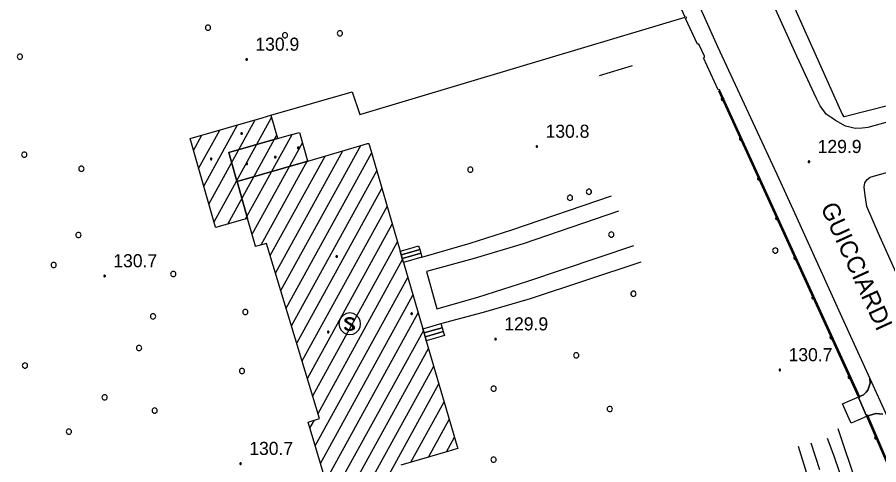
# Model space of a CAD drawing. Extents: x 513373 to 514978, y 5038576 to 5040180.
# Drawn here: x 513452.1 to 513550.7, y 5038668.6 to 5038719.9 of the extents above; entities that cross this region are included whole.
import ezdxf

# ---------------------------------------------------------------- set-up
doc = ezdxf.new("R2010")
doc.units = 0
for name, color, linetype in [('2010300', 7, 'Continuous'), ('3010204', 7, 'Continuous'), ('3030201', 7, 'Continuous'), ('B1211', 7, 'Continuous'), ('B12210', 7, 'Continuous'), ('C1131', 7, 'Continuous'), ('C12211', 7, 'Continuous'), ('C211113', 7, 'Continuous'), ('C211123', 7, 'Continuous'), ('C2911', 7, 'Continuous'), ('CAMP_C12211', 7, 'Continuous'), ('Default', 7, 'Continuous'), ('F12107', 7, 'Continuous'), ('F12131', 7, 'Continuous'), ('F12132', 7, 'Continuous'), ('G4315', 7, 'Continuous'), ('TOP500', 7, 'Continuous'), ('TOP920', 7, 'Continuous')]:
    doc.layers.add(name, color=color, linetype=linetype)

# ---------------------------------------------------------------- blocks, each defined once
blk = doc.blocks.new('CAMP_2F84D089')
at = {"layer": 'CAMP_C12211'}
for p, q in [((-7.696, 40.351), (-1.13, 52.294)), ((-8.876, 44.431), (-5.017, 51.451)), ((-8.286, 42.391), (-2.981, 52.04)), ((-9.467, 46.471), (-7.052, 50.862)), ((-4.088, 40.686), (1.234, 50.367)), ((-10.057, 48.511), (-9.088, 50.273)), ((-6.124, 40.097), (-0.544, 50.246)), ((-3.345, 38.924), (2.412, 49.395)), ((-0.656, 34.474), (7.048, 48.488)), ((-0.049, 32.464), (9.092, 49.092)), ((-2.306, 37.701), (3.005, 47.36)), ((-1.264, 36.483), (5.005, 47.885)), ((0.558, 30.455), (10.327, 48.226)), ((1.165, 28.446), (10.921, 46.191)), ((1.772, 26.437), (11.514, 44.157)), ((2.379, 24.428), (12.107, 42.122)), ((2.987, 22.418), (12.7, 40.088)), ((3.594, 20.409), (13.294, 38.053)), ((4.201, 18.4), (13.887, 36.019)), ((3.872, 14.688), (14.48, 33.984)), ((4.477, 12.675), (15.073, 31.95)), ((5.082, 10.661), (15.666, 29.915)), ((5.687, 8.648), (16.26, 27.88)), ((1.258, -2.521), (16.853, 25.846)), ((1.852, -4.554), (17.446, 23.811)), ((2.446, -6.588), (18.039, 21.777)), ((14.819, 12.805), (18.633, 19.742)), ((3.267, 16.702), (3.78, 17.634)), ((16.856, 13.396), (19.226, 17.708)), ((18.893, 13.988), (19.819, 15.673))]:
    blk.add_line(p, q, dxfattribs=at)
blk = doc.blocks.new('03080200')
at = {"layer": 'Default'}
for p, q in [((-0.139, 0.046), (-0.146, 0)), ((-0.146, 0), (-0.139, -0.046)), ((-0.118, 0.086), (-0.139, 0.046)), ((-0.086, 0.118), (-0.118, 0.086)), ((-0.046, 0.139), (-0.086, 0.118)), ((0, 0.146), (-0.046, 0.139)), ((-0.042, 0.014), (-0.045, 0)), ((-0.045, 0), (-0.042, -0.014)), ((-0.036, 0.026), (-0.042, 0.014)), ((-0.026, 0.036), (-0.036, 0.026)), ((-0.014, 0.042), (-0.026, 0.036)), ((0, 0.045), (-0.014, 0.042)), ((0.046, 0.139), (0, 0.146)), ((0.014, 0.042), (0, 0.045)), ((0.026, 0.036), (0.014, 0.042)), ((0.036, 0.026), (0.026, 0.036)), ((0.042, 0.014), (0.036, 0.026)), ((0.045, 0), (0.042, 0.014)), ((0.042, -0.014), (0.045, 0)), ((0.086, 0.118), (0.046, 0.139)), ((0.118, 0.086), (0.086, 0.118)), ((0.139, 0.046), (0.118, 0.086)), ((0.146, 0), (0.139, 0.046)), ((0.139, -0.046), (0.146, 0)), ((-0.139, -0.046), (-0.118, -0.086)), ((-0.118, -0.086), (-0.086, -0.118)), ((-0.086, -0.118), (-0.046, -0.139)), ((-0.046, -0.139), (0, -0.146)), ((-0.042, -0.014), (-0.036, -0.026)), ((-0.036, -0.026), (-0.026, -0.036)), ((-0.026, -0.036), (-0.014, -0.042)), ((-0.014, -0.042), (0, -0.045)), ((0, -0.045), (0.014, -0.042)), ((0, -0.146), (0.046, -0.139)), ((0.014, -0.042), (0.026, -0.036)), ((0.026, -0.036), (0.036, -0.026)), ((0.036, -0.026), (0.042, -0.014)), ((0.046, -0.139), (0.086, -0.118)), ((0.086, -0.118), (0.118, -0.086)), ((0.118, -0.086), (0.139, -0.046))]:
    blk.add_line(p, q, dxfattribs=at)
blk = doc.blocks.new('08020400')
at = {"layer": 'Default'}
for p, q in [((-0.086, 0.028), (-0.09, 0)), ((-0.09, 0), (-0.086, -0.028)), ((-0.073, 0.053), (-0.086, 0.028)), ((-0.053, 0.073), (-0.073, 0.053)), ((-0.028, 0.086), (-0.053, 0.073)), ((0, 0.09), (-0.028, 0.086)), ((0.028, 0.086), (0, 0.09)), ((0.053, 0.073), (0.028, 0.086)), ((0.073, 0.053), (0.053, 0.073)), ((0.086, 0.028), (0.073, 0.053)), ((0.09, 0), (0.086, 0.028)), ((0.086, -0.028), (0.09, 0)), ((-0.086, -0.028), (-0.073, -0.053)), ((-0.073, -0.053), (-0.053, -0.073)), ((-0.053, -0.073), (-0.028, -0.086)), ((-0.028, -0.086), (0, -0.09)), ((0, -0.09), (0.028, -0.086)), ((0.028, -0.086), (0.053, -0.073)), ((0.053, -0.073), (0.073, -0.053)), ((0.073, -0.053), (0.086, -0.028))]:
    blk.add_line(p, q, dxfattribs=at)
blk = doc.blocks.new('NSIMB25')
at = {"layer": 'Default'}
for p, q in [((-0.086, 0.028), (-0.09, 0)), ((-0.09, 0), (-0.086, -0.028)), ((-0.073, 0.053), (-0.086, 0.028)), ((-0.053, 0.073), (-0.073, 0.053)), ((-0.028, 0.086), (-0.053, 0.073)), ((0, 0.09), (-0.028, 0.086)), ((0.028, 0.086), (0, 0.09)), ((0.053, 0.073), (0.028, 0.086)), ((0.073, 0.053), (0.053, 0.073)), ((0.086, 0.028), (0.073, 0.053)), ((0.09, 0), (0.086, 0.028)), ((0.086, -0.028), (0.09, 0)), ((-0.086, -0.028), (-0.073, -0.053)), ((-0.073, -0.053), (-0.053, -0.073)), ((-0.053, -0.073), (-0.028, -0.086)), ((-0.028, -0.086), (0, -0.09)), ((0, -0.09), (0.028, -0.086)), ((0.028, -0.086), (0.053, -0.073)), ((0.053, -0.073), (0.073, -0.053)), ((0.073, -0.053), (0.086, -0.028))]:
    blk.add_line(p, q, dxfattribs=at)
blk = doc.blocks.new('05010100')
at = {"layer": 'Default'}
for p, q in [((-0.143, 0.046), (-0.15, 0)), ((-0.15, 0), (-0.143, -0.046)), ((-0.121, 0.088), (-0.143, 0.046)), ((-0.088, 0.121), (-0.121, 0.088)), ((-0.046, 0.143), (-0.088, 0.121)), ((0, 0.15), (-0.046, 0.143)), ((0.046, 0.143), (0, 0.15)), ((0.088, 0.121), (0.046, 0.143)), ((0.121, 0.088), (0.088, 0.121)), ((0.143, 0.046), (0.121, 0.088)), ((0.15, 0), (0.143, 0.046)), ((0.143, -0.046), (0.15, 0)), ((-0.143, -0.046), (-0.121, -0.088)), ((-0.121, -0.088), (-0.088, -0.121)), ((-0.088, -0.121), (-0.046, -0.143)), ((-0.046, -0.143), (0, -0.15)), ((0, -0.15), (0.046, -0.143)), ((0.046, -0.143), (0.088, -0.121)), ((0.088, -0.121), (0.121, -0.088)), ((0.121, -0.088), (0.143, -0.046))]:
    blk.add_line(p, q, dxfattribs=at)
blk = doc.blocks.new('03030201')
at = {"layer": 'Default'}
for p, q in [((-0.728, 1.001), (-1.001, 0.728)), ((-0.382, 1.177), (-0.728, 1.001)), ((0, 1.237), (-0.382, 1.177)), ((0.382, 1.177), (0, 1.237)), ((0.728, 1.001), (0.382, 1.177)), ((1.001, 0.728), (0.728, 1.001)), ((-1.177, 0.382), (-1.238, 0)), ((-1.238, 0), (-1.177, -0.382)), ((-1.001, 0.728), (-1.177, 0.382)), ((-0.518, 0.508), (-0.368, 0.643)), ((-0.518, 0.358), (-0.518, 0.508)), ((-0.443, 0.223), (-0.518, 0.358)), ((-0.333, 0.584), (-0.451, 0.478)), ((-0.451, 0.478), (-0.451, 0.376)), ((-0.451, 0.376), (-0.389, 0.265)), ((-0.368, 0.148), (-0.443, 0.223)), ((-0.389, 0.265), (-0.326, 0.201)), ((-0.298, 0.526), (-0.383, 0.448)), ((-0.383, 0.448), (-0.383, 0.394)), ((-0.383, 0.394), (-0.335, 0.306)), ((-0.368, 0.643), (-0.158, 0.718)), ((0.148, -0.186), (-0.368, 0.148)), ((-0.335, 0.306), (-0.287, 0.257)), ((-0.147, 0.651), (-0.333, 0.584)), ((-0.326, 0.201), (0.183, -0.128)), ((-0.135, 0.583), (-0.298, 0.526)), ((-0.287, 0.257), (-0.18, 0.198)), ((-0.18, 0.198), (0.337, -0.137)), ((-0.158, 0.718), (0.127, 0.718)), ((0.115, 0.651), (-0.147, 0.651)), ((0.103, 0.583), (-0.135, 0.583)), ((0.266, 0.526), (0.103, 0.583)), ((0.301, 0.584), (0.115, 0.651)), ((0.127, 0.718), (0.337, 0.643)), ((0.487, 0.327), (0.266, 0.526)), ((0.487, 0.418), (0.301, 0.584)), ((0.337, 0.643), (0.487, 0.508)), ((0.487, 0.508), (0.487, 0.327)), ((1.177, 0.382), (1.001, 0.728)), ((1.238, 0), (1.177, 0.382)), ((1.177, -0.382), (1.238, 0)), ((-1.177, -0.382), (-1.001, -0.728)), ((-1.001, -0.728), (-0.728, -1.001)), ((-0.518, -0.39), (-0.298, -0.588)), ((-0.518, -0.572), (-0.518, -0.39)), ((-0.333, -0.647), (-0.518, -0.481)), ((-0.368, -0.707), (-0.518, -0.572)), ((-0.158, -0.782), (-0.368, -0.707)), ((-0.147, -0.714), (-0.333, -0.647)), ((-0.298, -0.588), (-0.135, -0.647)), ((0.127, -0.782), (-0.158, -0.782)), ((0.115, -0.714), (-0.147, -0.714)), ((-0.135, -0.647), (0.103, -0.647)), ((0.103, -0.647), (0.266, -0.588)), ((0.301, -0.647), (0.115, -0.714)), ((0.337, -0.707), (0.127, -0.782)), ((0.254, -0.245), (0.148, -0.186)), ((0.183, -0.128), (0.295, -0.191)), ((0.302, -0.293), (0.254, -0.245)), ((0.266, -0.588), (0.352, -0.512)), ((0.295, -0.191), (0.357, -0.253)), ((0.419, -0.542), (0.301, -0.647)), ((0.352, -0.382), (0.302, -0.293)), ((0.337, -0.137), (0.412, -0.212)), ((0.487, -0.572), (0.337, -0.707)), ((0.352, -0.512), (0.352, -0.382)), ((0.357, -0.253), (0.419, -0.364)), ((0.412, -0.212), (0.487, -0.347)), ((0.419, -0.364), (0.419, -0.542)), ((0.487, -0.347), (0.487, -0.572)), ((0.728, -1.001), (1.001, -0.728)), ((1.001, -0.728), (1.177, -0.382)), ((-0.728, -1.001), (-0.382, -1.177)), ((-0.382, -1.177), (0, -1.238)), ((0, -1.238), (0.382, -1.177)), ((0.382, -1.177), (0.728, -1.001))]:
    blk.add_line(p, q, dxfattribs=at)
blk = doc.blocks.new('A$C3704598A')
at = {"layer": '2010300'}
blk.add_lwpolyline([(159.28, -668.58), (157.61, -664.912), (157.649, -664.896), (157.676, -664.875), (157.694, -664.852), (157.708, -664.827), (157.716, -664.798), (157.718, -664.757), (157.71, -664.72), (157.115, -663.41), (157.095, -663.38), (157.064, -663.352), (157.038, -663.338), (157.01, -663.329), (156.98, -663.327), (156.95, -663.33), (156.918, -663.339), (155.546, -660.402)], dxfattribs=at)
at = {"layer": '3010204'}
for points in [[(108.065, -671.485), (117.392, -668.786), (118.252, -671.393), (135.839, -666.132), (155.513, -660.257)], [(145.704, -666.928), (149.468, -665.776)], [(125.366, -687.738), (130.905, -686.134), (135.677, -684.617), (147.054, -680.722)], [(147.862, -682.475), (136.965, -686.206), (131.332, -687.879), (125.887, -689.368)], [(127.083, -693.673), (131.761, -692.317), (137.51, -690.506), (149.641, -686.401)], [(127.534, -695.325), (132.397, -694.041), (137.796, -692.459), (150.477, -688.273)], [(125.887, -689.368), (127.083, -693.673)], [(130.78, -763.373), (132.923, -761.13), (134.586, -759.538), (137.271, -757.48), (140.294, -755.605), (143.656, -753.598), (146.655, -751.79), (150.994, -749.135), (156.469, -745.856), (160.764, -743.2), (164.309, -740.923), (166.605, -739.336), (169.269, -737.051), (171.844, -734.517), (173.213, -732.901), (174.681, -730.267), (175.954, -726.593), (176.68, -723.592), (176.702, -720.811), (176.296, -717.936), (175.153, -713.79), (173.012, -707.42)], [(171.782, -708.472), (172.512, -710.49), (173.705, -713.959), (174.69, -717.991), (175.004, -721.069), (174.821, -724.119), (174.14, -727.369), (173.19, -730.21), (171.108, -733.178), (167.941, -736.272), (164.686, -739.027), (159.868, -742.062), (153.485, -745.877), (149.737, -748.062), (145.259, -751.056), (140.307, -753.932), (136.309, -756.274), (133.443, -758.512), (130.755, -760.841), (129.156, -762.908)], [(169.896, -709.001), (170.888, -712.066)], [(168.448, -709.407), (169.416, -712.491)]]:
    blk.add_lwpolyline(points, dxfattribs=at)
at = {"layer": 'B1211'}
for points in [[(166.592, -655.895), (173.493, -671.359), (173.58, -671.554), (173.604, -671.588), (173.627, -671.606), (173.658, -671.621), (173.664, -671.623), (173.69, -671.63), (173.727, -671.63), (194.458, -666.341)], [(178.888, -672.206), (176.406, -672.89), (176.1, -672.93), (175.755, -672.975), (174.978, -672.987), (174.361, -672.84), (173.877, -672.725), (172.726, -672.083), (172.349, -671.829), (171.665, -671.369), (170.95, -670.389), (170.541, -669.571), (168.285, -664.691), (160.651, -647.821), (151.346, -627.269), (142.537, -607.914), (132.751, -586.689), (123.465, -566.119), (117.038, -551.754), (103.489, -521.985), (94.591, -502.503), (88.175, -488.246)], [(149.774, -642.531), (159.201, -663.609), (164.009, -673.958), (165.987, -678.214), (168.048, -682.75), (173.428, -694.594), (176.643, -701.645), (176.682, -702.174), (176.42, -702.978), (176.22, -703.198), (175.939, -703.506), (175.48, -703.709), (175.303, -703.319), (159.493, -668.631), (159.46, -668.591), (159.437, -668.574), (159.405, -668.56), (159.372, -668.553), (159.335, -668.556), (159.28, -668.58), (157.61, -664.912), (157.649, -664.896), (157.676, -664.875), (157.694, -664.852), (157.708, -664.827), (157.716, -664.798), (157.718, -664.757), (157.71, -664.72), (157.115, -663.41), (157.095, -663.38), (157.064, -663.352), (157.038, -663.338), (157.01, -663.329), (156.98, -663.327), (156.95, -663.33), (156.918, -663.339), (155.546, -660.402), (155.592, -660.384), (155.619, -660.363), (155.641, -660.334), (155.659, -660.291), (155.662, -660.25), (155.653, -660.208)], [(181.686, -694.052), (177.638, -685.035), (176.325, -681.916), (176.255, -681.662), (176.135, -680.686), (176.018, -679.726), (176.094, -679.203), (176.35, -678.825), (176.678, -678.575), (177.061, -678.467), (182.4, -676.957)], [(178.147, -705.709), (177.382, -705.641), (177.34, -705.655), (176.58, -705.898), (176.443, -705.942), (176.427, -705.912), (176.408, -705.889), (176.399, -705.882), (176.385, -705.871), (176.359, -705.858), (176.331, -705.849), (176.288, -705.847), (176.248, -705.857), (175.404, -703.896), (175.437, -703.874), (175.467, -703.84), (175.483, -703.804), (175.49, -703.771), (175.489, -703.741), (175.48, -703.709), (175.939, -703.506), (176.22, -703.198), (176.42, -702.978), (176.682, -702.174), (176.643, -701.645), (178.598, -705.932)], [(179.442, -712.916), (176.443, -705.942), (176.58, -705.898), (177.34, -705.655), (177.382, -705.641), (178.147, -705.709)]]:
    blk.add_lwpolyline(points, dxfattribs=at)
at = {"layer": 'B12210'}
for points in [[(125.366, -687.738), (123.249, -688.341), (123.235, -688.292), (123.118, -687.893), (122.997, -687.476), (122.874, -687.055), (123.979, -686.728), (124.984, -686.432), (125.111, -686.865), (125.233, -687.283), (125.351, -687.685)], [(126.938, -697.01), (125.866, -697.317), (125.852, -697.266), (125.734, -696.862), (125.603, -696.414), (125.469, -695.956), (126.532, -695.631), (127.534, -695.325), (127.68, -695.82), (127.811, -696.267), (127.945, -696.721)]]:
    blk.add_lwpolyline(points, close=True, dxfattribs=at)
at = {"layer": 'C1131'}
for points in [[(108.828, -674.152), (103.248, -675.751), (104.186, -679.035), (104.201, -679.087), (105.402, -683.29), (104.394, -683.581), (101.763, -684.343), (101.747, -684.291), (98.817, -674.161), (107.057, -671.777), (108.065, -671.485), (108.814, -674.103)], [(112.292, -676.74), (104.201, -679.087), (104.186, -679.035), (103.248, -675.751), (108.828, -674.152), (110.321, -673.725), (111.329, -673.436), (112.275, -676.683)]]:
    blk.add_lwpolyline(points, close=True, dxfattribs=at)
blk.add_lwpolyline([(114.522, -713.949), (112.322, -706.625), (113.647, -706.225), (107.587, -686.17), (106.575, -686.444), (106.324, -686.512), (106.314, -686.477), (105.402, -683.29), (104.201, -679.087), (112.292, -676.74), (118.261, -674.978), (119.127, -674.722), (119.274, -674.705), (119.302, -674.803), (119.315, -674.848), (122.874, -687.055), (122.997, -687.476), (123.118, -687.893), (123.235, -688.292), (123.249, -688.341), (125.469, -695.956), (125.603, -696.414), (125.734, -696.862), (125.852, -697.266), (125.866, -697.317), (129.404, -709.45), (129.424, -709.518), (129.466, -709.662), (129.327, -709.714), (128.338, -710.001), (122.96, -711.563)], dxfattribs=at)
at = {"layer": 'C12211'}
blk.add_lwpolyline([(114.522, -713.949), (112.322, -706.625), (113.647, -706.225), (107.587, -686.17), (106.575, -686.444), (106.324, -686.512), (106.314, -686.477), (105.402, -683.29), (104.394, -683.581), (101.763, -684.343), (101.747, -684.291), (98.817, -674.161), (107.057, -671.777), (108.065, -671.485), (108.814, -674.103), (108.828, -674.152), (110.321, -673.725), (111.329, -673.436), (112.275, -676.683), (112.292, -676.74), (118.261, -674.978), (119.127, -674.722), (119.274, -674.705), (119.302, -674.803), (119.315, -674.848), (122.874, -687.055), (122.997, -687.476), (123.118, -687.893), (123.235, -688.292), (123.249, -688.341), (125.469, -695.956), (125.603, -696.414), (125.734, -696.862), (125.852, -697.266), (125.866, -697.317), (129.404, -709.45), (129.424, -709.518), (129.466, -709.662), (129.327, -709.714), (128.338, -710.001), (122.96, -711.563)], dxfattribs=at)
at = {"layer": 'C211113'}
blk.add_lwpolyline([(176.163, -706.048), (175.49, -706.342), (175.216, -706.461), (174.502, -706.772), (174.426, -706.597), (173.539, -704.539), (174.397, -704.171), (175.206, -703.824), (175.34, -703.762), (175.404, -703.896), (176.248, -705.857), (176.303, -705.995)], close=True, dxfattribs=at)
at = {"layer": 'C211123'}
for points in [[(125.111, -686.865), (124.104, -687.156), (122.997, -687.476), (122.874, -687.055), (123.979, -686.728), (124.984, -686.432)], [(125.233, -687.283), (124.226, -687.573), (123.118, -687.893), (122.997, -687.476), (124.104, -687.156), (125.111, -686.865)], [(125.366, -687.738), (123.249, -688.341), (123.235, -688.292), (123.118, -687.893), (124.226, -687.573), (125.233, -687.283), (125.351, -687.685)], [(127.68, -695.82), (126.673, -696.108), (125.603, -696.414), (125.469, -695.956), (126.532, -695.631), (127.534, -695.325)], [(127.811, -696.267), (126.804, -696.555), (125.734, -696.862), (125.603, -696.414), (126.673, -696.108), (127.68, -695.82)], [(127.945, -696.721), (126.938, -697.01), (125.866, -697.317), (125.852, -697.266), (125.734, -696.862), (126.804, -696.555), (127.811, -696.267)]]:
    blk.add_lwpolyline(points, close=True, dxfattribs=at)
at = {"layer": 'C2911'}
for points in [[(155.513, -660.257), (145.906, -639.271), (145.782, -639), (131.459, -607.71)], [(175.34, -703.762), (159.362, -668.703)], [(129.493, -768.231), (138.486, -767.517), (158.144, -766.013), (189.264, -763.627), (189.631, -763.599), (190.369, -763.543), (197.35, -752.142), (188.981, -734.343), (179.304, -712.974), (176.303, -705.995)]]:
    blk.add_lwpolyline(points, dxfattribs=at)
at = {"layer": '3030201'}
blk.add_blockref('03030201', (117.106, -695.372), dxfattribs=at)
at = {"layer": 'C2911'}
for p, rotation in [((159.789, -669.639), 114.50008052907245), ((161.862, -674.189), 114.50008052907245), ((163.936, -678.739), 114.50008052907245), ((166.009, -683.288), 114.50008052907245), ((168.083, -687.838), 114.50008052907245), ((170.156, -692.388), 114.50008052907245), ((172.23, -696.938), 114.50008052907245), ((174.303, -701.488), 114.50008052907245), ((177.349, -708.427), 113.27004175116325)]:
    blk.add_blockref('03080200', p, dxfattribs=dict(at, rotation=rotation))
at = {"layer": 'CAMP_C12211'}
blk.add_blockref('CAMP_2F84D089', (109.269, -724.04), dxfattribs=at)
at = {"layer": 'F12107'}
for p in [(105.3, -665.086), (138.522, -675.062), (169.68, -676.806), (89.031, -689.896), (133.799, -697.129), (166.345, -700.663), (104.599, -711.398)]:
    blk.add_blockref('08020400', p, dxfattribs=at)
at = {"layer": 'F12131'}
for p in [(104.721, -673.573), (108.576, -676.275), (115.612, -687.663)]:
    blk.add_blockref('NSIMB25', p, dxfattribs=at)
at = {"layer": 'F12132'}
for p in [(111.209, -675.205), (101.233, -676.484), (105.32, -677.038), (124.197, -694.211), (114.637, -696.315)]:
    blk.add_blockref('NSIMB25', p, dxfattribs=at)
at = {"layer": 'G4315', "xscale": 2, "yscale": 2}
for p in [(100.872, -661.447), (115.97, -662.09), (109.685, -662.309), (79.328, -664.773), (79.833, -675.991), (86.375, -677.614), (130.905, -677.704), (142.308, -680.938), (144.481, -680.251), (86.043, -685.196), (147.042, -685.147), (165.825, -686.978), (83.198, -688.64), (96.896, -689.672), (149.587, -691.939), (94.581, -694.529), (105.148, -694.018), (92.98, -698.145), (143.03, -698.983), (79.909, -700.153), (104.769, -700.786), (133.573, -702.807), (89.034, -703.802), (94.764, -705.311), (146.88, -705.136), (84.939, -707.723), (133.561, -710.933)]:
    blk.add_blockref('05010100', p, dxfattribs=at)
at = {"layer": 'TOP500'}
blk.add_text('GUICCIARDI', height=2, rotation=294.56647, dxfattribs=at).set_placement((170.97, -682.016))
at = {"layer": 'TOP920'}
for s, p in [('130.9', (106.3, -664.086)), ('130.8', (139.522, -674.062)), ('129.9', (170.68, -675.806)), ('130.7', (90.031, -688.896)), ('129.9', (134.799, -696.129)), ('130.7', (167.345, -699.663)), ('130.7', (105.599, -710.398))]:
    blk.add_text(s, height=1.5, dxfattribs=at).set_placement(p)

msp = doc.modelspace()

# ---------------------------------------------------------------- block references
at = {"layer": 'Default'}
msp.add_blockref('A$C3704598A', (513373.046, 5039380.14), dxfattribs=at)

doc.saveas('drawing.dxf')
